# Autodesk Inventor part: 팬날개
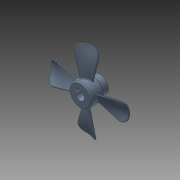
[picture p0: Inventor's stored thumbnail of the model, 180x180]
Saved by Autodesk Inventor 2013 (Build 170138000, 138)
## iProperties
Company: 한국ATC센터
Created: 2016-06
Part Number: 팬날개
Document SubType Name: Modeling
Designer: mdu
Density: 1.06 g/cm^3
Material: ABS 플라스틱
Mass: 29.2868 g
Surface Area: 147.721 cm^2
Volume: 27.6291 cm^3
Author: mdu
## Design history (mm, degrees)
sketch "스케치1"
  geometry: L1 (-15, 0)-(15, 0); L2 (-15, 0)-(-15, 17); L3 (-15, 17)-(5, 17); L4 (5, 17)-(5, 13); L5 (5, 13)-(15, 13); L6 (15, 13)-(15, 0); 2 further points
  constraints: 12 end point, 3 parallel, 2 perpendicular, 1 coincident, 1 horizontal, 1 midpoint
  dimensions: "d0" = 30 distance of L1.start L1.end; "d8" = 34 diameter of L3 L1; "d10" = 26 diameter of L5 L1; "d32" = 20 distance of L2.end L3.end
revolve "회전1" sketch "스케치1" stored, may be unused: angle "d11" = 90 deg
node "작업 평면2"
sketch "스케치7"
  geometry: L1 (-15, 17)-(5, 17) reference; L2 (-15, -17)-(5, -17) reference; L3 (-5, 17)-(-5, -17); A1 r 35 centre (-36.399, -13.457) between (-2, -7) and (-8, 7); 1 further point
  constraints: 2 end point, 2 midpoint, 2 point on circle, 1 centre point
  dimensions: "d36" = 35 radius of A1; "d37" = 10 distance from line of A1.start L2; "d38" = 10 distance from line of A1.end L1; "d45" = 3 distance from line of A1.end L3; "d46" = 3 distance from line of A1.start L3
sketch "3D 스케치1"
  geometry: L1 through (0, 0) direction (1, 0) reference; L2 through (0, 0) direction (1, 0) reference; 13 other entities
  constraints: 2 collinear
  node "투영 원본 위치 스케치7"
sketch "스케치8"
  geometry: L1 (-15, 17)-(5, 17) reference; L2 (-15, -17)-(5, -17) reference; L3 (-5, 17)-(-5, -17); A1 r 30 centre (-28.74, -3.591) between (-3, -19) and (-9, 19); 1 further point
  constraints: 2 end point, 2 midpoint, 2 point on circle, 1 centre point
  dimensions: "d43" = 30 radius of A1; "d47" = 4 distance from line of A1.end L3; "d48" = 2 distance from line of A1.start L3; "d58" = 2 distance from line of A1.end L1; "d59" = 2 distance from line of A1.start L2
sketch "3D 스케치2"
sketch "3D 스케치3"
feature "경계 패치1" sketch "3D 스케치2", "3D 스케치3" dims "d50" = 0
feature "연장1" dims "d55" = 2
feature "두껍게 하기1" dims "d51" = 2, "d52" = 2
sketch "스케치9"
  geometry: C1 r 59 at (0, 0); 1 further point
  constraints: 1 centre point, 1 coincident
  dimensions: "d60" = 118 diameter of C1
extrude "돌출2" sketch "스케치9" distance "d62" = 200; taper "d63" = 0 deg
fillet "모깎기6" dims "d64" = 10
fillet "모깎기7" dims "d66" = 0.8
fillet "모깎기8" dims "d67" = 0.8
sketch "스케치2"
  geometry: L1 (-2.5, 6)-(-2.5, 8.8); L2 (-2.5, 8.8)-(2.5, 8.8); L3 (2.5, 8.8)-(2.5, 6); A1 r 6.5 centre (0, 0) between (-2.5, 6) and (2.5, 6); 1 further point
  constraints: 6 end point, 2 parallel, 2 point on circle, 1 centre point, 1 coincident, 1 horizontal, 1 vertical
  dimensions: "d12" = 13 diameter of A1; "d13" = 5 distance of L1.end L2.end; "d14" = 15.3 dimension on A1 L2 (computed from d12)
extrude "돌출1" cut sketch "스케치2" stored distance "d15" = 10; taper "d16" = 0 deg
chamfer "모따기1" distance "d17" = 1; stored, may be unused: second distance "d18" = 2, angle "d19" = 45 deg
node "작업 평면1"
fillet "모깎기9" dims "d77" = 2
fillet "모깎기10" dims "d78" = 2
fillet "모깎기11" dims "d79" = 2
node "솔리드1"
pattern_circular "원형 패턴1" dims "d69" = 360 deg
pattern_circular "원형 패턴2" dims angle "d72" = 360 deg
pattern_circular "원형 패턴3" dims angle "d75" = 360 deg
node "투영 원본 위치 스케치8"
node "곡면1"
node "곡면2"
node "곡면3"
node "곡면4"
feature "경계 패치2"
feature "경계 패치3"
feature "경계 패치4"
